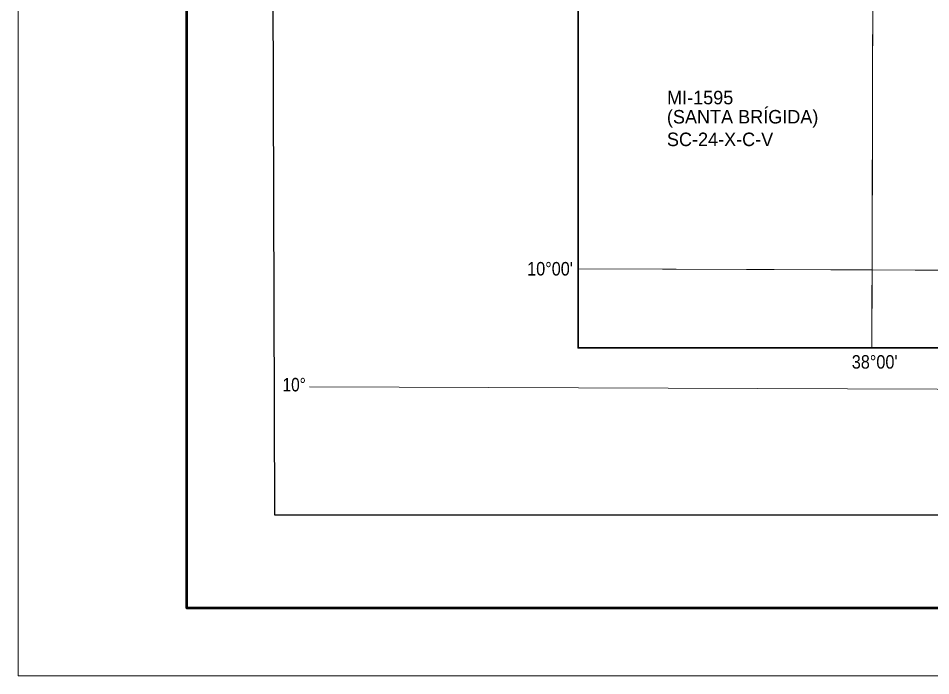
# Model space of a CAD drawing. Extents: x 553962 to 842807, y 8883888 to 9032388.
# Drawn here: x 553962 to 587759, y 8883888 to 8908228 of the extents above; entities that cross this region are included whole.
import ezdxf
from ezdxf.enums import TextEntityAlignment as Align

# ---------------------------------------------------------------- set-up
doc = ezdxf.new("R2010")
doc.units = 0
doc.header["$LTSCALE"] = 200
for name, color, linetype, lineweight in [('1', 7, 'Continuous', 13), ('3', 7, 'Continuous', 13), ('6', 7, 'Continuous', 13)]:
    doc.layers.add(name, color=color, linetype=linetype, lineweight=lineweight)
doc.layers.add('46', color=7, linetype='Continuous')

msp = doc.modelspace()

# ---------------------------------------------------------------- linework, layer by layer
at = {"layer": '1'}
msp.add_lwpolyline([(564751.7, 8894587.5), (664411.9, 8894209.9), (791388.5, 8893536.2)], dxfattribs=at)
at = {"layer": '3'}
msp.add_lwpolyline([(842807.3, 9032387.8), (842807.3, 8883887.8), (553961.7, 8883887.8), (553961.7, 9032387.8)], close=True, dxfattribs=at)
at = {"layer": '3', "lineweight": 53}
msp.add_lwpolyline([(840307.3, 9029887.8), (840307.3, 8886387.8), (560211.7, 8886387.8), (560211.7, 9029887.8)], close=True, dxfattribs=at)
at = {"layer": '3', "lineweight": 25}
msp.add_lwpolyline([(563033.9, 9026438.8), (793061.1, 9026438.8), (793495.6, 8889836.8), (563468.3, 8889836.8)], close=True, dxfattribs=at)
at = {"layer": '6', "lineweight": 35}
msp.add_lwpolyline([(574695.3, 8924769.6), (626625.7, 8924769.6), (626625.7, 8896026.7), (574695.3, 8896026.7)], close=True, dxfattribs=at)
at = {"layer": '6'}
for points in [[(585656.3, 8924738.8), (585614.8, 8909969.8), (585573.6, 8896026.7)], [(574695.3, 8898953.2), (596544.3, 8898870.4), (626625.7, 8898710.8)]]:
    msp.add_lwpolyline(points, dxfattribs=at)
for points in [[(596575.8, 8909932.4), (585614.8, 8909969.8), (585583.8, 8898914.4), (596544.8, 8898874.9)], [(585583.8, 8898914.4), (574695.3, 8898953.2), (574695.3, 8896026.7), (585573.6, 8896026.7)]]:
    msp.add_lwpolyline(points, close=True, dxfattribs=at)

# ---------------------------------------------------------------- texts
at = {"layer": '46', "width": 0.85}
msp.add_text('10°', height=500, dxfattribs=at).set_placement((564183.6, 8894414.2), align=Align.CENTER)
at = {"layer": '6'}
for s, p in [('MI-1595', (577992.4, 8905041.6)), ('(SANTA BRÍGIDA)', (577987.1, 8904332)), ('SC-24-X-C-V', (577987.1, 8903494.9))]:
    msp.add_text(s, height=500, dxfattribs=at).set_placement(p)
at = {"layer": '6', "width": 0.9}
for s, p in [("10°00'", (573657.3, 8898704.5)), ("38°00'", (585681.9, 8895256.8))]:
    msp.add_text(s, height=500, dxfattribs=at).set_placement(p, align=Align.CENTER)

doc.saveas('drawing.dxf')
